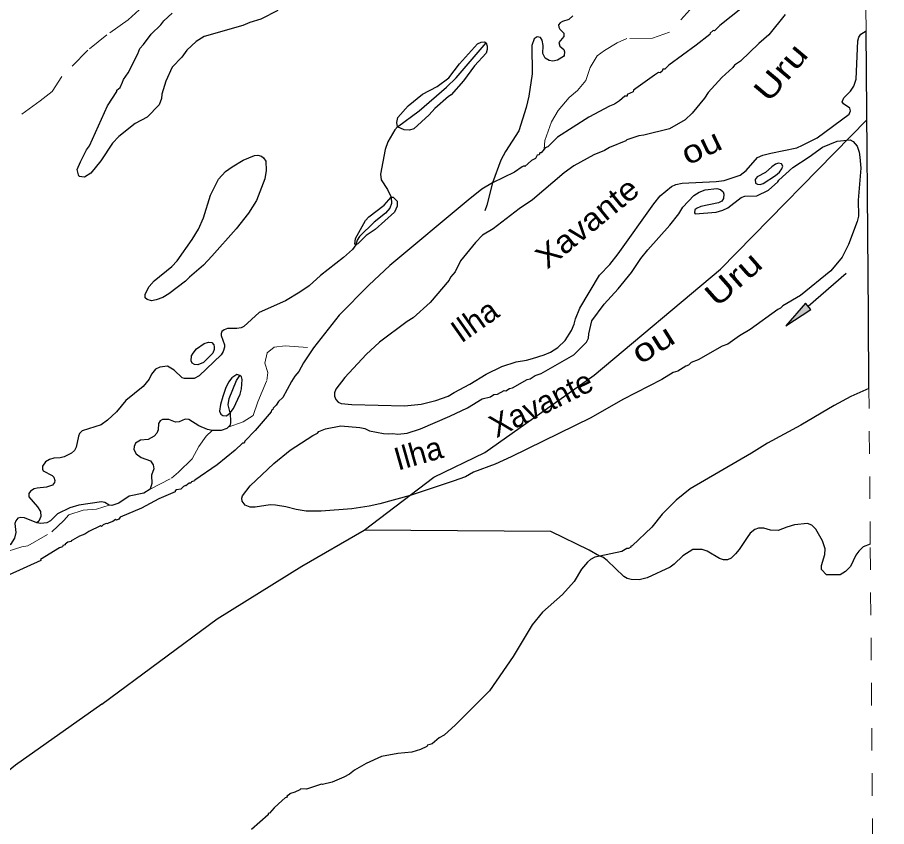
# Model space of a CAD drawing. Extents: x 344.9 to 371, y 7566.4 to 7594.3.
# Drawn here: x 367.111 to 370.961, y 7574.277 to 7577.861 of the extents above; entities that cross this region are included whole.
import ezdxf
from ezdxf.enums import TextEntityAlignment as Align

# ---------------------------------------------------------------- set-up
doc = ezdxf.new("R2010")
doc.units = 0
doc.header["$LTSCALE"] = 0.04
doc.linetypes.add('SHORT_DASHED', pattern=[2.7, 1.5, -1.2])
for name, color, linetype, lineweight in [('10', 7, 'Continuous', 25), ('17', 7, 'SHORT_DASHED', 13), ('2', 7, 'Continuous', 25), ('53', 7, 'SHORT_DASHED', 13), ('55', 7, 'Continuous', 25), ('7', 7, 'Continuous', 25)]:
    doc.layers.add(name, color=color, linetype=linetype, lineweight=lineweight)
doc.layers.add('61', color=7, linetype='Continuous')

msp = doc.modelspace()

# ---------------------------------------------------------------- hatches: boundary and pattern name
at = {"layer": '10'}
msp.add_hatch(color=256, dxfattribs=at).paths.add_polyline_path([(370.5153, 7576.4951), (370.626, 7576.5666), (370.6019, 7576.5945)])

# ---------------------------------------------------------------- linework, layer by layer
msp.add_line((370.7819, 7576.726), (370.614, 7576.5805), dxfattribs=at)
msp.add_lwpolyline([(370.5153, 7576.4951), (370.626, 7576.5666), (370.6019, 7576.5945)], close=True, dxfattribs=at)
at = {"layer": '17'}
for points in [[(367.65, 7577.8943), (367.6018, 7577.8501), (367.5074, 7577.7839), (367.423, 7577.7156), (367.3085, 7577.599), (367.2643, 7577.5327), (367.2121, 7577.4906), (367.0173, 7577.349)], [(370.1166, 7577.9232), (370.0001, 7577.7946), (369.9237, 7577.7686), (369.8108, 7577.7668), (369.7673, 7577.7477), (369.7117, 7577.7147), (369.6787, 7577.6904), (369.6474, 7577.6383), (369.6283, 7577.5809), (369.5918, 7577.5375), (369.5554, 7577.5062), (369.5067, 7577.4489), (369.4772, 7577.3985), (369.4476, 7577.3151), (369.4439, 7577.2773)], [(368.0441, 7576.0464), (368.1109, 7576.07), (368.1553, 7576.0972), (368.1753, 7576.158), (368.2161, 7576.2523), (368.2198, 7576.2877), (368.2071, 7576.3295), (368.2171, 7576.3753), (368.2479, 7576.3998), (368.2969, 7576.4062), (368.4218, 7576.3971)], [(367.6986, 7575.7718), (367.793, 7575.8203), (367.8247, 7575.8466), (367.8855, 7575.9065), (367.9145, 7575.9605), (367.9472, 7576.0067), (367.9744, 7576.032)], [(366.9919, 7575.4754), (367.0379, 7575.4866), (367.1305, 7575.5166), (367.1577, 7575.5202), (367.2629, 7575.5823), (367.3165, 7575.6332), (367.3382, 7575.6581), (367.4017, 7575.6781), (367.4607, 7575.6826), (367.5177, 7575.7012)]]:
    msp.add_lwpolyline(points, dxfattribs=at)
at = {"layer": '2'}
for points in [[(370.6017, 7578.3083), (370.4994, 7578.1148), (370.4597, 7578.0552), (370.4446, 7578.0377), (370.4422, 7578.0282), (370.4303, 7578.0226), (370.4287, 7578.0139), (370.3652, 7577.94), (370.2223, 7577.8241), (370.1984, 7577.8011), (370.1929, 7577.8019), (370.1794, 7577.7908), (370.1786, 7577.7844), (370.1182, 7577.7375), (369.9968, 7577.6486), (369.9785, 7577.6311), (369.9705, 7577.6319), (369.9674, 7577.6232), (369.9586, 7577.6145), (369.9507, 7577.6168), (369.9324, 7577.6041)], [(368.2652, 7577.8906), (368.1895, 7577.8525), (368.141, 7577.8376), (368.11, 7577.8241), (367.9385, 7577.7757), (367.9027, 7577.7534), (367.8614, 7577.7153)], [(367.5763, 7577.574), (367.5811, 7577.5859), (367.601, 7577.6145), (367.6446, 7577.6987), (367.6526, 7577.7225), (367.6692, 7577.7399), (367.7034, 7577.7868), (367.7463, 7577.8281), (367.759, 7577.8448), (367.7963, 7577.8789)], [(370.5121, 7577.8733), (370.4398, 7577.7828), (370.3953, 7577.7447), (370.3144, 7577.6661), (370.2866, 7577.6486), (370.2794, 7577.6383), (370.2318, 7577.5938), (370.1714, 7577.5287), (370.1539, 7577.5025), (370.1, 7577.4366), (370.0682, 7577.4064), (369.9999, 7577.3675), (369.8856, 7577.3389), (369.8633, 7577.3365), (369.8109, 7577.3183), (369.8053, 7577.3135), (369.7339, 7577.2841), (369.7109, 7577.2706), (369.664, 7577.2524)], [(369.7717, 7576.8137), (369.9294, 7577.0352), (369.9575, 7577.07), (370.0082, 7577.1113), (370.0281, 7577.121), (370.0553, 7577.1266), (370.2056, 7577.1336), (370.2411, 7577.138), (370.3118, 7577.1622), (370.3385, 7577.182), (370.3897, 7577.2404), (370.4132, 7577.251), (370.4478, 7577.2598), (370.5632, 7577.2831), (370.589, 7577.2946), (370.6531, 7577.3276), (370.7953, 7577.4322), (370.8004, 7577.4474), (370.7976, 7577.458), (370.7695, 7577.4772), (370.7648, 7577.4868), (370.7722, 7577.5039), (370.8017, 7577.5343), (370.8155, 7577.556), (370.8261, 7577.5869), (370.8335, 7577.7575), (370.8377, 7577.7725), (370.8469, 7577.7859), (370.8702, 7577.8004)], [(370.883, 7576.2179), (370.8804, 7576.543), (370.8702, 7577.8004)], [(368.7952, 7577.3756), (368.792, 7577.3954), (368.7966, 7577.4167), (368.8423, 7577.4691), (368.906, 7577.5201), (368.971, 7577.5545), (369.0227, 7577.5935), (369.0693, 7577.6555), (369.1491, 7577.7428), (369.1648, 7577.7509), (369.18, 7577.7523), (369.1869, 7577.7481)], [(369.1869, 7577.7481), (369.192, 7577.7333), (369.192, 7577.7181), (369.1869, 7577.702), (369.1358, 7577.6463), (369.0869, 7577.5794), (369.0325, 7577.5183), (369.0212, 7577.5101)], [(367.8614, 7577.7153), (367.8392, 7577.6844), (367.7971, 7577.6399), (367.7685, 7577.578), (367.7511, 7577.5208), (367.7494, 7577.5017), (367.7391, 7577.4739), (367.6852, 7577.4191), (367.632, 7577.3905), (367.5597, 7577.3334), (367.5327, 7577.304), (367.4811, 7577.2254), (367.4358, 7577.1714), (367.4088, 7577.1531), (367.385, 7577.1563), (367.381, 7577.1634), (367.3762, 7577.1864), (367.3898, 7577.2214), (367.4167, 7577.2746), (367.4302, 7577.2913), (367.5104, 7577.4684), (367.551, 7577.5319), (367.5517, 7577.5383), (367.5668, 7577.5501), (367.5763, 7577.574)], [(369.9324, 7577.6041), (369.8403, 7577.5382), (369.8379, 7577.5311), (369.8125, 7577.5192), (369.8117, 7577.512), (369.8022, 7577.5113), (369.7784, 7577.4906), (369.7561, 7577.4763), (369.7331, 7577.4675), (369.6426, 7577.4183), (369.5036, 7577.3302), (369.4599, 7577.2881), (369.4488, 7577.2834), (369.4439, 7577.2773)], [(369.0212, 7577.5101), (368.9594, 7577.4574), (368.9345, 7577.4284), (368.8676, 7577.3675), (368.8473, 7577.3611), (368.8238, 7577.362), (368.7952, 7577.3756)], [(369.7716, 7576.6592), (369.8307, 7576.7315), (369.8728, 7576.7934), (369.903, 7576.8307), (370.0007, 7576.9411), (370.0404, 7576.9912), (370.0579, 7577.0205), (370.1077, 7577.0717), (370.1312, 7577.086), (370.1575, 7577.097), (370.2092, 7577.1024), (370.2258, 7577.0991), (370.2373, 7577.0885), (370.2405, 7577.0774), (370.2387, 7577.058), (370.2309, 7577.0472), (370.217, 7577.0388), (370.1382, 7577.0229), (370.1197, 7577.0146), (370.1109, 7577.0081), (370.11, 7576.9948), (370.1137, 7576.9902), (370.2065, 7576.998), (370.2351, 7577.0063), (370.2581, 7577.0179), (370.3167, 7577.0638), (370.3333, 7577.0691), (370.3866, 7577.0705), (370.4383, 7577.0959), (370.4795, 7577.1325), (370.4835, 7577.1404), (370.5462, 7577.1952), (370.6177, 7577.2428), (370.6764, 7577.2865), (370.7416, 7577.3119), (370.7995, 7577.3183), (370.8131, 7577.3111), (370.8313, 7577.2905), (370.84, 7577.2635), (370.8432, 7577.2413), (370.8464, 7577.1936), (370.8353, 7577.0507)], [(369.4439, 7577.2773), (369.4305, 7577.2603), (369.425, 7577.2611), (369.4218, 7577.2516), (369.4139, 7577.2508), (369.4052, 7577.2357), (369.3877, 7577.227), (369.3583, 7577.2008), (369.3551, 7577.2031), (369.3472, 7577.1992), (369.3123, 7577.1753), (369.2148, 7577.1275)], [(369.664, 7577.2524), (369.5759, 7577.2039), (369.5322, 7577.1729), (369.3924, 7577.053), (369.3337, 7577.0133), (369.2177, 7576.9244), (369.1709, 7576.8959), (369.1399, 7576.8633), (369.074, 7576.7823), (369.0502, 7576.7339), (369.0295, 7576.7108), (369.0232, 7576.6973), (368.9398, 7576.598), (368.8644, 7576.5298), (368.8374, 7576.5139), (368.7156, 7576.4226), (368.6561, 7576.3684), (368.5606, 7576.2654), (368.5209, 7576.2139), (368.5158, 7576.1989), (368.5158, 7576.1832), (368.5209, 7576.1689), (368.5324, 7576.1567), (368.5449, 7576.1511), (368.5924, 7576.147), (368.8249, 7576.1413), (368.9001, 7576.148), (368.9647, 7576.1635), (369.0196, 7576.184), (369.045, 7576.2002), (369.1151, 7576.236), (369.188, 7576.2805), (369.2563, 7576.3153), (369.3209, 7576.3358), (369.3661, 7576.3425), (369.3929, 7576.3499), (369.4436, 7576.3658), (369.4722, 7576.3783), (369.5054, 7576.3988), (369.5368, 7576.4298), (369.5649, 7576.4743), (369.5778, 7576.5027), (369.5834, 7576.5262), (369.6019, 7576.573), (369.6896, 7576.7196), (369.7357, 7576.7664), (369.7717, 7576.8137)], [(369.2148, 7577.1275), (369.1686, 7577.0993), (369.1072, 7577.0506), (368.7599, 7576.7616), (368.6677, 7576.6749), (368.5358, 7576.5418), (368.4218, 7576.3971)], [(368.6099, 7576.8529), (368.6053, 7576.8571), (368.6085, 7576.8813), (368.6524, 7576.9614), (368.6681, 7576.9773), (368.7359, 7577.0297), (368.7659, 7577.065)], [(368.7659, 7577.065), (368.7756, 7577.065), (368.7926, 7577.0475), (368.7931, 7577.0249), (368.781, 7576.9988)], [(370.8353, 7577.0507), (370.8369, 7576.9808), (370.8313, 7576.957), (370.7924, 7576.8554), (370.7646, 7576.7982), (370.7146, 7576.7386), (370.5796, 7576.6298), (370.5018, 7576.5837), (370.4914, 7576.5734), (370.4795, 7576.5679), (370.3573, 7576.4781), (370.3096, 7576.4503), (370.2572, 7576.413), (370.2333, 7576.4051), (370.1262, 7576.3447), (370.0952, 7576.3328), (370.0841, 7576.3201), (370.0714, 7576.3161), (370.0357, 7576.2947), (370.0158, 7576.2875), (369.965, 7576.2566), (369.7922, 7576.169), (369.6511, 7576.0878), (369.298, 7575.9151)], [(368.781, 7576.9988), (368.6951, 7576.9211), (368.6556, 7576.8951), (368.6196, 7576.8584), (368.6099, 7576.8529)], [(368.4189, 7576.0088), (368.4403, 7576.0191), (368.4467, 7576.0263), (368.4753, 7576.039), (368.5436, 7576.0525), (368.6278, 7576.0445), (368.65, 7576.0398), (368.6706, 7576.0303), (368.7326, 7576.0183), (368.7532, 7576.016), (368.7739, 7576.0184), (368.7961, 7576.0152), (368.8374, 7576.0191), (368.8962, 7576.039), (369.0264, 7576.0954), (369.1042, 7576.1319), (369.1701, 7576.1716), (369.2058, 7576.1803), (369.2209, 7576.1907), (369.2376, 7576.193), (369.267, 7576.2081), (369.2741, 7576.2073), (369.29, 7576.2169), (369.3043, 7576.2208), (369.3694, 7576.2566), (369.3829, 7576.2606), (369.4044, 7576.2756), (369.4306, 7576.2844), (369.5759, 7576.367), (369.6322, 7576.4226), (369.641, 7576.44), (369.6426, 7576.4591), (369.656, 7576.5171), (369.71, 7576.5901), (369.7716, 7576.6592)], [(368.4218, 7576.3971), (368.3785, 7576.3304), (368.3577, 7576.2923), (368.3403, 7576.2725), (368.3252, 7576.2487), (368.2863, 7576.178), (368.268, 7576.1605), (368.2577, 7576.1438), (368.2434, 7576.1296), (368.2426, 7576.124), (368.237, 7576.1216), (368.2347, 7576.1145), (368.1648, 7576.0311), (368.1187, 7575.9842), (368.1156, 7575.9747), (368.1084, 7575.9755), (368.0758, 7575.9437), (367.9956, 7575.8794), (367.8964, 7575.8119), (367.8956, 7575.8079), (367.8821, 7575.804), (367.8789, 7575.7984), (367.8725, 7575.7984)], [(368.0966, 7576.2756), (368.0823, 7576.2789), (368.0606, 7576.2648), (368.0458, 7576.2459), (368.032, 7576.2175), (368.0209, 7576.1813)], [(368.0527, 7576.1093), (368.0675, 7576.1289), (368.0971, 7576.1923), (368.104, 7576.2161), (368.1067, 7576.2576), (368.103, 7576.2683), (368.0966, 7576.2756)], [(370.883, 7576.2179), (370.803, 7576.1816), (370.7292, 7576.1421), (370.5811, 7576.0553), (370.433, 7575.9746), (370.3624, 7575.9305), (370.0911, 7575.7727), (370.0284, 7575.7235), (369.9675, 7575.6606), (369.9205, 7575.603), (369.8347, 7575.5205), (369.8284, 7575.5189), (369.8276, 7575.5141), (369.8181, 7575.5093), (369.8101, 7575.5094), (369.7887, 7575.4951), (369.6903, 7575.4743)], [(368.0209, 7576.1813), (368.0103, 7576.1462), (368.0066, 7576.1167), (368.0117, 7576.1033), (368.0214, 7576.0973), (368.0371, 7576.0964), (368.0527, 7576.1093)], [(369.298, 7575.9151), (369.2272, 7575.8826), (369.1312, 7575.8468), (369.0954, 7575.8262), (369.0407, 7575.8071), (368.8501, 7575.7436), (368.7167, 7575.7063), (368.669, 7575.6967), (368.5928, 7575.684), (368.4562, 7575.6737), (368.3895, 7575.6745), (368.3451, 7575.6809), (368.3006, 7575.6936), (368.2545, 7575.7015), (368.2307, 7575.7023), (368.164, 7575.6912), (368.1418, 7575.6912), (368.1195, 7575.7007), (368.1068, 7575.719), (368.1052, 7575.7325), (368.1084, 7575.742), (368.1425, 7575.7857), (368.2474, 7575.8849), (368.3196, 7575.9437), (368.4189, 7576.0088)], [(367.8725, 7575.7984), (367.8575, 7575.7857), (367.8551, 7575.7881), (367.8464, 7575.7841), (367.8344, 7575.7722), (367.8162, 7575.7683), (367.8098, 7575.7643), (367.8098, 7575.7603), (367.7368, 7575.7285), (367.6606, 7575.688), (367.5668, 7575.6483), (367.5605, 7575.6388), (367.5494, 7575.6348), (367.5462, 7575.6372), (367.5343, 7575.6285), (367.5129, 7575.6213), (367.5121, 7575.6181), (367.5041, 7575.6189), (367.4914, 7575.6142), (367.4834, 7575.6062), (367.4795, 7575.6086), (367.4271, 7575.5848), (367.4096, 7575.5729), (367.3866, 7575.5642), (367.3556, 7575.5451), (367.3484, 7575.5435), (367.3485, 7575.5395), (367.335, 7575.5371), (367.3231, 7575.5284), (367.3222, 7575.5244), (367.3127, 7575.5221), (367.3112, 7575.5165), (367.2968, 7575.5117), (367.2127, 7575.4609), (367.2143, 7575.4554), (367.0745, 7575.3926)], [(369.6903, 7575.4743), (369.6692, 7575.4698), (369.6498, 7575.4599), (369.636, 7575.4484), (369.6092, 7575.4177), (369.5765, 7575.3635), (369.5258, 7575.3047), (369.4362, 7575.2269), (369.391, 7575.1702), (369.3075, 7575.0301), (369.2024, 7574.878), (369.0521, 7574.7283), (369.0009, 7574.6819), (368.9787, 7574.6708), (368.9486, 7574.6446), (368.9279, 7574.6375), (368.9246, 7574.6316), (368.8969, 7574.6182), (368.8586, 7574.6074), (368.7954, 7574.6016), (368.7238, 7574.5874), (368.6555, 7574.5572), (368.6047, 7574.5271), (368.5825, 7574.5104), (368.5563, 7574.4969), (368.5046, 7574.4746), (368.4626, 7574.4635), (368.4578, 7574.4659), (368.3911, 7574.4437)], [(368.3911, 7574.4437), (368.3665, 7574.4453), (368.3617, 7574.4397), (368.3403, 7574.4302), (368.3157, 7574.423), (368.3157, 7574.4199), (368.3045, 7574.4119), (368.3053, 7574.4071), (368.2974, 7574.4056), (368.2839, 7574.3937), (368.2481, 7574.3611), (368.2275, 7574.3373), (368.2211, 7574.3349), (368.2211, 7574.3293), (368.1474, 7574.264)]]:
    msp.add_lwpolyline(points, dxfattribs=at)
for points in [[(367.9725, 7576.803), (367.9351, 7576.7635), (367.8728, 7576.7107), (367.8553, 7576.6923), (367.781, 7576.6361), (367.7556, 7576.6209), (367.7256, 7576.6096), (367.7048, 7576.6055), (367.6855, 7576.611), (367.6772, 7576.6193), (367.6772, 7576.6336), (367.6836, 7576.6498), (367.6942, 7576.6683), (367.7168, 7576.6939), (367.7957, 7576.7574), (367.8192, 7576.7826), (367.8857, 7576.8777), (367.9138, 7576.9236), (367.9355, 7576.9728), (367.9664, 7577.0739), (368.002, 7577.1443), (368.0329, 7577.1782), (368.0624, 7577.1995), (368.1113, 7577.2283), (368.1607, 7577.2486), (368.1759, 7577.2505), (368.1925, 7577.2461), (368.2017, 7577.2388), (368.211, 7577.2245), (368.2123, 7577.1822), (368.2063, 7577.1455), (368.1699, 7577.0495), (368.1344, 7576.9939), (368.0804, 7576.9241)], [(370.4525, 7577.1984), (370.4252, 7577.1742), (370.3883, 7577.1544), (370.3787, 7577.1424), (370.3805, 7577.1269), (370.3893, 7577.1214), (370.4004, 7577.1209), (370.4142, 7577.125), (370.4691, 7577.1608), (370.4866, 7577.1756), (370.4968, 7577.1894), (370.5009, 7577.2019), (370.4954, 7577.212), (370.4829, 7577.2148), (370.4686, 7577.2106)], [(367.91, 7576.3228), (367.8948, 7576.3242), (367.8846, 7576.3297), (367.88, 7576.3403), (367.8814, 7576.3618), (367.8888, 7576.3738), (367.9045, 7576.3928), (367.9386, 7576.4165), (367.9571, 7576.423), (367.9728, 7576.4216), (367.9811, 7576.4105), (367.982, 7576.4015), (367.982, 7576.3899), (367.976, 7576.3733), (367.9353, 7576.332)]]:
    msp.add_lwpolyline(points, close=True, dxfattribs=at)
at = {"layer": '53'}
for points in [[(370.8702, 7577.8004), (370.8647, 7578.4736), (370.863, 7578.6751), (370.8604, 7578.9949), (370.8546, 7579.7184), (370.8491, 7580.3875)], [(370.8804, 7576.543), (370.8734, 7577.4069), (370.8702, 7577.8004)], [(370.9611, 7566.6143), (370.8886, 7575.5281), (370.883, 7576.2179), (370.8804, 7576.543)]]:
    msp.add_lwpolyline(points, dxfattribs=at)
at = {"layer": '55'}
for points in [[(368.7952, 7577.3756), (368.89, 7577.4471), (369.0121, 7577.5511), (369.0545, 7577.5935), (369.1869, 7577.7481)], [(367.4854, 7574.8196), (367.9953, 7575.1968), (368.3712, 7575.4312), (368.6469, 7575.5903), (368.956, 7575.8248), (369.1816, 7575.9336), (369.6662, 7576.2769), (370.2259, 7576.7458), (370.8734, 7577.4069)], [(369.2148, 7577.1275), (369.1908, 7577.0286), (369.1814, 7577.0045)], [(368.7659, 7577.065), (368.7686, 7577.0372), (368.7602, 7577.0161), (368.7412, 7576.994), (368.6917, 7576.9535), (368.6265, 7576.8909), (368.6165, 7576.8735), (368.6099, 7576.8529)], [(368.0527, 7576.1093), (368.0452, 7576.1456), (368.0497, 7576.1731), (368.0817, 7576.2526), (368.0966, 7576.2756)], [(369.6899, 7575.4744), (369.6436, 7575.5014), (369.4741, 7575.5842), (368.6469, 7575.5903)], [(367.4854, 7574.8196), (367.1023, 7574.5489), (366.6611, 7574.1888), (366.3867, 7573.8395), (366.1501, 7573.478), (365.7032, 7572.9063), (365.6623, 7572.8301), (365.4153, 7572.3691)]]:
    msp.add_lwpolyline(points, dxfattribs=at)
at = {"layer": '7'}
msp.add_line((369.6903, 7575.4743), (369.6899, 7575.4744), dxfattribs=at)
for points in [[(369.5714, 7577.8681), (369.5539, 7577.851), (369.5253, 7577.8418), (369.5156, 7577.8367), (369.5082, 7577.8274), (369.5087, 7577.8178), (369.5138, 7577.8086), (369.5313, 7577.7902), (369.5309, 7577.7763), (369.5087, 7577.7491), (369.5138, 7577.7329), (369.5313, 7577.7182), (369.535, 7577.7085), (369.5322, 7577.6915), (369.5298, 7577.6868), (369.5036, 7577.6709), (369.4822, 7577.6669), (369.4671, 7577.6701), (369.4488, 7577.6796), (369.4385, 7577.701), (369.4393, 7577.7368), (369.4361, 7577.7598), (369.4282, 7577.7709), (369.4139, 7577.7749), (369.3996, 7577.7654), (369.39, 7577.7368), (369.391, 7577.6106), (369.3762, 7577.5123), (369.3651, 7577.4622), (369.3324, 7577.3588), (369.2728, 7577.2674), (369.2525, 7577.2279), (369.2148, 7577.1275)], [(368.7952, 7577.3756), (368.7832, 7577.3629), (368.7516, 7577.3096), (368.7405, 7577.2762), (368.7199, 7577.1671), (368.7217, 7577.1417), (368.7508, 7577.099), (368.7659, 7577.065)], [(368.6099, 7576.8529), (368.5948, 7576.8323), (368.5559, 7576.7967), (368.4535, 7576.7171), (368.4028, 7576.6721), (368.3627, 7576.6442), (368.2986, 7576.6052), (368.1819, 7576.5537), (368.1136, 7576.4918), (368.1016, 7576.4858), (368.0836, 7576.4826), (368.0421, 7576.4824), (368.0273, 7576.4773), (368.0172, 7576.4694), (368.0135, 7576.4616), (368.0135, 7576.4514), (368.0287, 7576.4101), (368.0287, 7576.4), (368.0228, 7576.3818), (368.0131, 7576.3665), (367.9158, 7576.2737), (367.8946, 7576.2622), (367.8507, 7576.261), (367.8415, 7576.2642), (367.8055, 7576.2984), (367.7751, 7576.3157), (367.7418, 7576.3125), (367.722, 7576.303), (367.7044, 7576.2813), (367.6943, 7576.2587), (367.668, 7576.2257), (367.5918, 7576.1638), (367.5503, 7576.1144), (367.5102, 7576.0772), (367.482, 7576.0571), (367.3972, 7576.0295), (367.3862, 7576.0179), (367.382, 7576.0064), (367.3714, 7575.9582), (367.3636, 7575.9434), (367.3502, 7575.9314), (367.3184, 7575.9146), (367.3004, 7575.9104), (367.2718, 7575.9095), (367.2529, 7575.9028), (367.2358, 7575.8922), (367.222, 7575.8733), (367.222, 7575.8603), (367.2257, 7575.8531), (367.2644, 7575.8324), (367.2718, 7575.8241), (367.2764, 7575.8102)], [(367.9744, 7576.032), (367.9536, 7576.0359), (367.9144, 7576.0516), (367.8702, 7576.0804), (367.854, 7576.0814), (367.8269, 7576.0701), (367.8112, 7576.0677), (367.7816, 7576.0807), (367.753, 7576.0799), (367.7429, 7576.0739), (367.736, 7576.0624), (367.7346, 7576.0343), (367.7291, 7576.0193), (367.7171, 7576.0064), (367.6903, 7575.9921), (367.6566, 7575.988), (367.634, 7575.9751), (367.6275, 7575.9607), (367.6271, 7575.9474), (367.6363, 7575.9275), (367.6585, 7575.9123), (367.7004, 7575.8964), (367.7124, 7575.8798), (367.7156, 7575.8622), (367.7045, 7575.8334), (367.7069, 7575.7967), (367.6986, 7575.7718)], [(368.0527, 7576.1093), (368.0551, 7576.0676), (368.0528, 7576.0552), (368.0441, 7576.0464)], [(368.0441, 7576.0464), (368.0385, 7576.0406), (368.0131, 7576.0319), (367.9744, 7576.032)], [(367.2764, 7575.8102), (367.2746, 7575.8007), (367.2663, 7575.7892), (367.2395, 7575.7804), (367.1984, 7575.7767), (367.185, 7575.7728), (367.1693, 7575.7631), (367.162, 7575.7525), (367.1615, 7575.7372), (367.1998, 7575.6941), (367.2127, 7575.6733), (367.215, 7575.65), (367.2053, 7575.6306), (367.1975, 7575.623)], [(367.6986, 7575.7718), (367.6704, 7575.7538), (367.6067, 7575.7404), (367.5601, 7575.7102), (367.5292, 7575.7), (367.5177, 7575.7012)], [(367.5177, 7575.7012), (367.4978, 7575.7127), (367.4835, 7575.715), (367.383, 7575.7009), (367.3429, 7575.6896), (367.2889, 7575.6631), (367.2575, 7575.6312), (367.2418, 7575.6231), (367.2141, 7575.6199), (367.1975, 7575.623)], [(367.1975, 7575.623), (367.143, 7575.6451), (367.1255, 7575.6467), (367.1135, 7575.6426), (367.1038, 7575.6315), (367.1001, 7575.619), (367.104, 7575.5797), (367.0976, 7575.5548), (367.08, 7575.5273), (367.0496, 7575.5056), (367.0034, 7575.4841), (366.9919, 7575.4754)], [(370.8886, 7575.5281), (370.8567, 7575.5165), (370.8376, 7575.4975), (370.8249, 7575.48), (370.8004, 7575.4299), (370.7789, 7575.4069), (370.7551, 7575.3918), (370.6955, 7575.3926), (370.6725, 7575.4165), (370.6725, 7575.4339), (370.6876, 7575.4823), (370.6892, 7575.507), (370.6772, 7575.5435), (370.6479, 7575.5951), (370.6296, 7575.6126), (370.6113, 7575.6197), (370.5526, 7575.6134), (370.5185, 7575.6038), (370.4811, 7575.5887), (370.4462, 7575.5895), (370.4168, 7575.5991), (370.3938, 7575.5983), (370.3771, 7575.5935), (370.3572, 7575.5761), (370.3429, 7575.5578), (370.308, 7575.5038), (370.2921, 7575.4847), (370.2731, 7575.4665), (370.2556, 7575.4593), (370.2382, 7575.4593), (370.2207, 7575.4649), (370.1659, 7575.4966), (370.1445, 7575.5046), (370.1031, 7575.5046), (370.0579, 7575.4768), (370.0206, 7575.4395), (370.0023, 7575.426), (369.8999, 7575.3791), (369.8649, 7575.3704), (369.83, 7575.372), (369.8125, 7575.3767), (369.7974, 7575.3855), (369.7235, 7575.4555), (369.7046, 7575.4698), (369.6903, 7575.4743)]]:
    msp.add_lwpolyline(points, dxfattribs=at)

# ---------------------------------------------------------------- texts
at = {"layer": '61'}
for s, rotation, width, p in [('Uru', 49.958, 1.3, (370.5298, 7577.586)), ('ou', 25.664, 1.2, (370.161, 7577.2425)), ('Xavante', 39.295, 1.1, (369.6659, 7576.9134)), ('Uru', 41.362, 1.3, (370.3147, 7576.6657)), ('ou', 32.088, 1.3, (369.9516, 7576.3724))]:
    msp.add_text(s, height=0.1, rotation=rotation, dxfattribs=dict(at, width=width)).set_placement(p, align=Align.CENTER)
for s, rotation, p in [('Ilha', 35.113, (369.1652, 7576.4778)), ('Xavante', 26.299, (369.4524, 7576.1058)), ('Ilha', 15.844, (368.9004, 7575.883))]:
    msp.add_text(s, height=0.1, rotation=rotation, dxfattribs=at).set_placement(p, align=Align.CENTER)

doc.saveas('drawing.dxf')
